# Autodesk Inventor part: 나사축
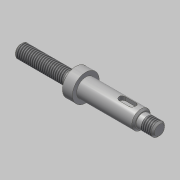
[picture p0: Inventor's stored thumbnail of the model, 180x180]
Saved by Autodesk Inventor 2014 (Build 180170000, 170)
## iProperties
Created: 2019-10
Part Number: 나사축
Material: 강철, 연강
Document SubType Name: Modeling
Designer: mduedu
Density: 1 g/cm^3
Appearance: 강철
Author: mduedu
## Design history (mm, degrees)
sketch "스케치1"
  geometry: L1 (0, 0)-(33, 0); L2 (33, 0)-(33, 4); L3 (33, 4)-(0, 4); L4 (0, 4)-(0, 0); L5 (33, 0)-(39, 0); L6 (39, 0)-(39, 8); L7 (39, 8)-(33, 8); L8 (33, 8)-(33, 0); L9 (39, 0)-(73, 0); L10 (73, 0)-(73, 5.5); L11 (73, 5.5)-(39, 5.5); L12 (39, 5.5)-(39, 0); L13 (73, 0)-(83, 0); L14 (83, 0)-(83, 4); L15 (83, 4)-(73, 4); L16 (73, 4)-(73, 0)
  constraints: 32 end point, 8 parallel, 4 horizontal, 4 perpendicular
  dimensions: "d0" = 83 distance between parallel lines of L14 L4; "d2" = 8 diameter of L15 L13; "d3" = 11 diameter of L11 L9; "d4" = 16 diameter of L7 L5; "d5" = 8 diameter of L3 L1; "d6" = 33 distance of L2.end L3.end; "d7" = 6 distance of L6.end L7.end; "d8" = 40 distance between parallel lines of L10 L8
revolve "회전1" sketch "스케치1" stored, may be unused: angle "d9" = 90 deg
sketch "스케치2"
  geometry: L1 (0, 4)-(0, -4) reference; L2 (0, -4)-(-33, -4) reference; L3 (-33, -4)-(-33, -8) reference; L4 (-33, -8)-(-39, -8) reference; L5 (-39, -8)-(-39, -5.5) reference; L6 (-39, -5.5)-(-73, -5.5) reference; L7 (-73, -5.5)-(-73, -4) reference; L8 (-73, -4)-(-83, -4) reference; L9 (-83, -4)-(-83, 4) reference; L10 (-83, 4)-(-73, 4) reference; L11 (-73, 4)-(-73, 5.5) reference; L12 (-73, 5.5)-(-39, 5.5) reference; L13 (-39, 5.5)-(-39, 8) reference; L14 (-39, 8)-(-33, 8) reference; L15 (-33, 8)-(-33, 4) reference; L16 (-33, 4)-(0, 4) reference; L17 (0, 0)-(-83, 0); L18 (-31, 3)-(-33, 3); L19 (-33, 3)-(-33, 4); L20 (-31, 3)-(-29.268, 4); L21 (-33, 4)-(-29.268, 4)
  constraints: 10 end point, 1 collinear, 1 midpoint, 1 point on line, 1 vertical
  dimensions: "d13" = 1 distance between parallel lines of L18 L21; "d15" = 30 deg angle of L16 L20; "d17" = 2 distance of L18.start L18.end
revolve "회전2" sketch "스케치2" stored, may be unused: angle "d12" = 90 deg
feature "스레드1" dims "d18" = 10, "d19" = 0
feature "스레드2" dims "d20" = 7, "d21" = 0
chamfer "모따기1" distance "d22" = 1; stored, may be unused: second distance "d23" = 2, angle "d24" = 30 deg
chamfer "모따기2" distance "d25" = 1; stored, may be unused: second distance "d26" = 2, angle "d27" = 30 deg
sketch "스케치3"
  geometry: L1 (-31, -3)-(-33, -3) reference; L2 (-33, -3)-(-33, -8) reference; L3 (-33, -8)-(-39, -8) reference; L4 (-39, -8)-(-39, -5.5) reference; L5 (-39, -5.5)-(-72, -5.5) reference; L6 (-72, -5.5)-(-73, -4.5) reference; L7 (-73, -4.5)-(-73, -4) reference; L8 (-73, -4)-(-82, -4) reference; L9 (-82, -4)-(-83, -3) reference; L10 (-83, -3)-(-83, 3) reference; L11 (-83, 3)-(-82, 4) reference; L12 (-82, 4)-(-73, 4) reference; L13 (-73, 4)-(-73, 4.5) reference; L14 (-73, 4.5)-(-72, 5.5) reference; L15 (-72, 5.5)-(-39, 5.5) reference; L16 (-39, 5.5)-(-39, 8) reference; L17 (-39, 8)-(-33, 8) reference; L18 (-33, 8)-(-33, 3) reference; L19 (-33, 3)-(-31, 3) reference; L20 (-31, 3)-(-29.268, 4) reference; L21 (-29.268, 4)-(-1, 4) reference; L22 (-1, 4)-(0, 3) reference; L23 (0, 3)-(0, -3) reference; L24 (0, -3)-(-1, -4) reference; L25 (-1, -4)-(-29.268, -4) reference; L26 (-29.268, -4)-(-31, -3) reference; L27 (-59, 5.5)-(-69, 5.5); L28 (-69, 5.5)-(-69, 3); L29 (-69, 3)-(-59, 3); L30 (-59, 3)-(-59, 5.5); 1 further point
  constraints: 8 end point, 2 parallel, 1 horizontal, 1 perpendicular, 1 point on line
  dimensions: "d28" = 20 distance between parallel lines of L30 L16; "d29" = 10 distance of L27.start L27.end; "d30" = 2.5 distance of L27.end L28.end
extrude "돌출1" cut sketch "스케치3" stored distance "d31" = 4; taper "d32" = 0 deg
fillet "모깎기1"
fillet "모깎기2"
node "솔리드1"
node "절단 모서리 투영1"
node "절단 모서리 투영2"
